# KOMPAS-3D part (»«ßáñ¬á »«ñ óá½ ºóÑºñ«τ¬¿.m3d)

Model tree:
1. Эскиз:1
2. Операция выдавливания:1
     Расстояние 1 = 12; Расстояние 2 = 64
3. Эскиз:2
4. Отверстие:1
5. Эскиз:3
6. Отверстие:2
7. Эскиз:4
8. Отверстие:3
9. Скругление:1
     Радиус = 0.2

Referenced files in C:\Program Files\ASCON\KOMPAS-3D V13 Home\Sys\: holelib.lfr
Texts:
  посадка под вал звездочки
  Сплав АЛ8  ГОСТ 1583-93
  Отверстие 01
  (вариант 1)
